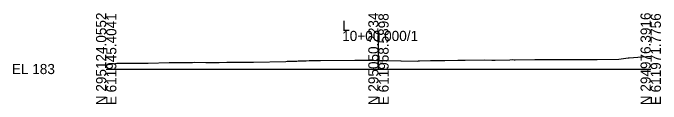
# Model space of a CAD drawing. Extents: x -81 to 616364, y 450 to 299952.
# Drawn here: x 535426.7 to 535605.2, y 114838.7 to 114863.9 of the extents above; entities that cross this region are included whole.
import ezdxf

# ---------------------------------------------------------------- set-up
doc = ezdxf.new("R2010")
doc.units = 0
for name, color, linetype in [('Exist XS Ground Line', 7, 'Continuous'), ('Old_Level_63', 7, 'Continuous'), ('Prop XS Side Slope Text', 7, 'Continuous')]:
    doc.layers.add(name, color=color, linetype=linetype)

msp = doc.modelspace()

# ---------------------------------------------------------------- linework, layer by layer
at = {"layer": 'Exist XS Ground Line'}
for points in [[(535585.54, 114850.97), (535586.57, 114851), (535587.11, 114851.02), (535587.65, 114851.03), (535593.59, 114851.11), (535594.24, 114851.14), (535596.16, 114851.45), (535596.38, 114851.49), (535600.01, 114851.71), (535602.36, 114851.88)], [(535452.36, 114849.5), (535455.31, 114850.02), (535463.94, 114849.97), (535469.67, 114850.15), (535473.86, 114850.18), (535474.96, 114850.17), (535476.17, 114850.2), (535476.71, 114850.21), (535479.8, 114850.18), (535480.65, 114850.17), (535483.43, 114850.19), (535485.59, 114850.22), (535486.33, 114850.23), (535486.91, 114850.26), (535489.08, 114850.24), (535489.89, 114850.25), (535490.82, 114850.26), (535492.95, 114850.29), (535501.84, 114850.47), (535502.2, 114850.52), (535502.51, 114850.52), (535504.83, 114850.56), (535505.27, 114850.61), (535505.69, 114850.59), (535506.79, 114850.61), (535507.41, 114850.61), (535508.23, 114850.67), (535509.1, 114850.7), (535509.81, 114850.72), (535510.84, 114850.74), (535511.4, 114850.74), (535520.81, 114850.8), (535521.04, 114850.81), (535521.2, 114850.81), (535521.5, 114850.81), (535525.14, 114850.77), (535525.25, 114850.77), (535527.36, 114850.75), (535528.04, 114850.74), (535529.99, 114850.7), (535533.48, 114850.63), (535533.63, 114850.62), (535538.23, 114850.57), (535538.42, 114850.61), (535538.68, 114850.64), (535541.65, 114850.75), (535542.17, 114850.75), (535545.61, 114850.7), (535549.18, 114850.81), (535551.27, 114850.81), (535556.54, 114850.88), (535558.6, 114850.85), (535559.52, 114850.82), (535563.58, 114850.94), (535564.35, 114850.95), (535564.75, 114850.91), (535565.01, 114850.91), (535570.44, 114851.02), (535570.54, 114851.03), (535574.8, 114851.02), (535574.94, 114851.02), (535580.14, 114851.02), (535580.52, 114851.03), (535580.79, 114851.03), (535585.54, 114850.97)]]:
    msp.add_lwpolyline(points, dxfattribs=at)
at = {"layer": 'Old_Level_63'}
for p, q in [((535527.36, 114848.36), (535527.36, 114858.9)), ((535452.36, 114848.36), (535527.36, 114848.36)), ((535527.36, 114848.36), (535602.36, 114848.36))]:
    msp.add_line(p, q, dxfattribs=at)

# ---------------------------------------------------------------- texts
for s, p in [('N 295124.0552', (535452.36, 114838.36)), ('E 611945.4041', (535455.16, 114838.36)), ('N 295050.2234', (535527.36, 114838.36)), ('E 611958.5898', (535530.16, 114838.37)), ('N 294976.3916', (535602.36, 114838.36)), ('E 611971.7756', (535605.16, 114838.36))]:
    msp.add_text(s, height=2.8, rotation=90, dxfattribs=at).set_placement(p)
for s, p in [('L', (535517.36, 114858.9)), ('10+00.000/1', (535517.36, 114856.1)), ('EL 183', (535426.36, 114846.96))]:
    msp.add_text(s, height=2.8, dxfattribs=at).set_placement(p)
at = {"layer": 'Prop XS Side Slope Text'}
msp.add_text('185.383', height=0.5, dxfattribs=at).set_placement((535526.17, 114849.89))

doc.saveas('drawing.dxf')
